// Mitsubishi GX Works2 project: 三菱回原点   PLC: FX1S

PROGRAM MAIN
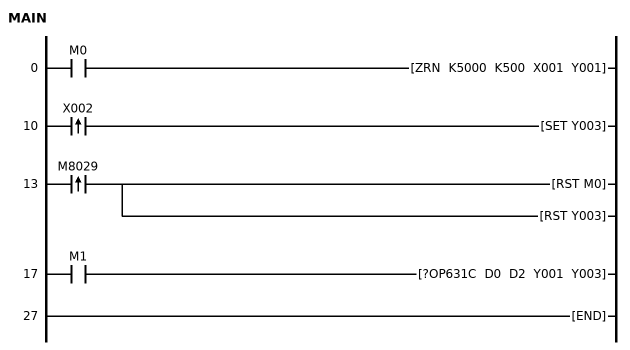
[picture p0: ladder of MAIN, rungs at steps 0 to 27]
0     LD      M0
      ZRN     K5000 K500 X001 Y001
10    LDP     X002
      SET     Y003
13    LDP     M8029
      RST     M0
      RST     Y003
17    LD      M1
      ?OP631C D0 D2 Y001 Y003
27    END
END_PROGRAM
